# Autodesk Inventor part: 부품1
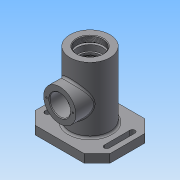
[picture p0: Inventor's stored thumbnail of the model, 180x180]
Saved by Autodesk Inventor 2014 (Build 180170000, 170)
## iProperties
Created: 2017-10
Part Number: 부품1
Material: 일반
Document SubType Name: Modeling
Designer: NET
Density: 1 g/cm^3
Appearance: 기본값
Author: NET
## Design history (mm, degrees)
sketch "스케치1"
  geometry: C1 r 31 at (0, 0); 1 further point
  constraints: 1 centre point, 1 coincident
  dimensions: "d0" = 62 diameter of C1
extrude "돌출1" new body sketch "스케치1" distance "d1" = 102; taper "d2" = 0 deg
sketch "스케치2"
  geometry: L1 (-58, 47)-(58, 47); L2 (58, 47)-(58, -47); L3 (58, -47)-(-58, -47); L4 (-58, -47)-(-58, 47); 3 further points
  constraints: 8 end point, 2 midpoint, 2 parallel, 1 horizontal, 1 horizontal alignment, 1 perpendicular, 1 vertical alignment
  dimensions: "d3" = 94 distance of L1.end L2.end; "d4" = 116 distance of L1.start L1.end
extrude "돌출2" join sketch "스케치2" distance "d5" = 13; taper "d6" = 0 deg
chamfer "모따기1" distance "d7" = 20; stored, may be unused: second distance "d8" = 2, angle "d9" = 45 deg
sketch "스케치3"
  geometry: L1 (-46, 20)-(-46, -20); L2 (-50, 20)-(-50, -20); L3 (-42, -20)-(-42, 20); L4 (-38, -47)-(-58, -27) reference; L5 (-38, -47)-(38, -47) reference; L6 (58, -27)-(38, -47) reference; L7 (58, -27)-(58, 27) reference; L8 (38, 47)-(58, 27) reference; L9 (38, 47)-(-38, 47) reference; L10 (-58, 27)-(-38, 47) reference; L11 (-58, 27)-(-58, -27) reference; C1 r 31 at (0, 0) reference; C2 r 31 at (0, 0) reference; A1 r 4 centre (-46, 20) between (-42, 20) and (-50, 20); A2 r 4 centre (-46, -20) between (-50, -20) and (-42, -20); 2 further points
  constraints: 8 end point, 4 point on circle, 4 tangent, 2 centre point, 1 horizontal alignment, 1 midpoint, 1 parallel, 1 vertical
  dimensions: "d10" = 46 distance of C1.centre point (-46, 0); "d11" = 4 radius of A1; "d12" = 20 vertical distance of L3.start point (-46, 0)
extrude "돌출3" cut sketch "스케치3" distance "d13" = 13; taper "d14" = 0 deg
sketch "스케치4"
  geometry: C1 r 35 at (0, 0); 1 further point
  constraints: 1 centre point, 1 coincident
  dimensions: "d15" = 70 diameter of C1
extrude "돌출4" join sketch "스케치4" distance "d16" = 3; taper "d17" = 0 deg
sketch "스케치5"
  geometry: L1 (0, 0)-(76, 0) reference; L2 (69, 102)-(7, 102) reference; C1 r 25 at (38, 46); 2 further points
  constraints: 1 centre point, 1 midpoint, 1 vertical alignment
  dimensions: "d18" = 50 diameter of C1; "d19" = 56 distance from line of C1.centre L2
extrude "돌출5" join sketch "스케치5" stored distance "d20" = 3; taper "d21" = 0 deg
hole "구멍1" diameter "d24" = 40.376; stored, may be unused: countersink angle "d28" = 90 deg, drill point angle "d30" = 0 deg; dims "d25" = 9, "d26" = 4, "d27" = 2, "d29" = 9, "d31" = 10, "d32" = 10
sketch "스케치6"
  geometry: L1 (0, 93)-(0, -16); L2 (-24, 93)-(-24, 90); L3 (-24, 90)-(-20, 90); L4 (-20, 90)-(-20, 81); L5 (-20, 81)-(-17.5, 81); L6 (-17.5, 81)-(-17.5, 77.75); L7 (-17.5, 77.75)-(-18.2, 77.75); L8 (-18.5, 77.45)-(-18.5, 76); L9 (-18.5, 76)-(-17.5, 76); L10 (-17.5, 76)-(-17.5, 65); L11 (-17.5, 65)-(-26, 65); L12 (-26, 65)-(-26, 27); L13 (-26, 27)-(-17.5, 27); L14 (-17.5, 27)-(-17.5, 16); L15 (-17.5, 16)-(-16.5, 16); L16 (-16.5, 16)-(-16.5, 11); L17 (-16.5, 11)-(-10, 11); L18 (-16, 1)-(-22, -16); L19 (-20.188, 102)-(20.188, 102) reference; L20 (20.188, 93)-(-20.188, 93) reference; L21 (-24, 93)-(0, 93); L22 (-35, -16)-(35, -16) reference; L23 (-16, 1)-(-13.2, 1); L24 (-12.5, 1.7)-(-12.5, 8); L25 (-12.2, 8.3)-(-10, 8.3); L26 (-10, 8.3)-(-10, 11); L27 (-12.5, 1.7)-(-13.2, 1); L28 (-22, -16)-(0, -16); A1 r 0.3 centre (-12.2, 8) between (-12.2, 8.3) and (-12.5, 8); A2 r 0.3 centre (-18.2, 77.45) between (-18.2, 77.75) and (-18.5, 77.45); 4 further points
  constraints: 50 end point, 14 parallel, 9 point on line, 4 perpendicular, 4 point on circle, 4 tangent, 3 collinear, 2 centre point, 2 midpoint, 2 vertical, 1 horizontal
  dimensions: "d34" = 48 diameter of L2 L1; "d35" = 3 distance of L2.start L2.end; "d36" = 21 distance between parallel lines of L5 L19; "d38" = 1.75 distance of point (-18.5, 77.75) L8.end; "d39" = 37 diameter of L8 L1; "d40" = 11 distance of L9.end L10.end; "d41" = 35 diameter of L10 L1; "d42" = 38 distance of L11.end L12.end; "d43" = 35 diameter of L14 L1; "d44" = 52 diameter of L12 L1; "d47" = 44 diameter of L18.end L1; "d48" = 32 diameter of L18.start L1; "d53" = 7.3 distance of point (-12.5, 1) point (-12.5, 8.3); "d54" = 2.7 distance of L25.end L17.end; "d55" = 20 diameter of L26 L1; "d56" = 25 diameter of L24 L1; "d57" = 0.3 radius of A1; "d58" = 0.7 distance of L24.start point (-12.5, 1); "d59" = 0.7 distance of L23.end point (-12.5, 1) (= d58); "d60" = 40 diameter of L4 L1; "d61" = 35 diameter of L6 L1; "d63" = 26 distance between parallel lines of L19 L9; "d66" = 33 diameter of L16 L1; "d67" = 5 distance of L15.end L16.end; "d102" = 0.3 radius of A2
revolve "회전1" sketch "스케치6" stored, may be unused: angle "d68" = 90 deg
hole "구멍2" diameter "d71" = 32; stored, may be unused: countersink angle "d75" = 90 deg, drill point angle "d77" = 0 deg; dims "d72" = 9, "d73" = 4, "d74" = 2, "d76" = 40, "d78" = 10, "d79" = 10
sketch "스케치7" dims "d80" = 41
  geometry: C1 r 16 at (0, 0) reference; 3 further points
  constraints: 2 horizontal alignment, 1 coincident, 2 other
hole "구멍3" sketch "스케치7" at (20.5, 0) diameter "d81" = 2.459; stored, may be unused: countersink angle "d85" = 90 deg, drill point angle "d87" = 118 deg; dims "d82" = 6, "d83" = 4, "d84" = 2, "d86" = 8
sketch "스케치8"
  geometry: L1 (102, -4)-(102, 58) reference; L2 (71, -20)-(21, -20) reference; 2 further points
  constraints: 1 other
  dimensions: "d93" = 56 distance from line of point (46, -10) L1; "d94" = 10 distance from line of point (46, -10) L2
feature "엠보싱1" sketch "스케치8" dims "d91" = 0.5, "d92" = 0
chamfer "모따기3" distance "d98" = 1; stored, may be unused: second distance "d99" = 2, angle "d100" = 45 deg
fillet "모깎기1" dims "d101" = 3
node "솔리드1"
mirror "대칭1"
pattern_circular "원형 패턴1" dims angle "d89" = 360 deg
node "투영된 루프1"
node "투영된 루프2"
node "투영된 루프3"
